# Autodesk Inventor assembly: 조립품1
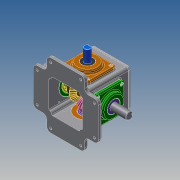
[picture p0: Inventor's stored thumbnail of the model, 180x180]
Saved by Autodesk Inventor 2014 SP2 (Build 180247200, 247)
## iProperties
Created: 2019-12
Part Number: 조립품1
Document SubType Name: Assembly
Designer: kb542-10
Mass: 4194.65 g
Surface Area: 3365.11 cm^2
Volume: 1062.39 cm^3
Density: 3.94832 g/cm^3
Author: kb542-10
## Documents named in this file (16)
- C:\Users\kb542-10\Desktop\391204V1038\조립도면.iam
- C:\Users\kb542-10\Desktop\391204V1038\본체.ipt
- C:\Users\kb542-10\Desktop\391204V1038\개스킷.ipt
- C:\Users\kb542-10\Desktop\391204V1038\메인베벨기어.ipt
- C:\Users\kb542-10\Desktop\391204V1038\메인축.ipt
- C:\Users\kb542-10\Desktop\391204V1038\메인커버.ipt
- C:\Users\kb542-10\Desktop\391204V1038\베어링 6203.ipt
- C:\Users\kb542-10\Desktop\391204V1038\베어링 6204.ipt
- C:\Users\kb542-10\Desktop\391204V1038\볼트 M4.ipt
- C:\Users\kb542-10\Desktop\391204V1038\상부커버.ipt
- C:\Users\kb542-10\Desktop\391204V1038\서브베벨기어.ipt
- C:\Users\kb542-10\Desktop\391204V1038\서브축.ipt
- C:\Users\kb542-10\Desktop\391204V1038\서브커버.ipt
- C:\Users\kb542-10\Desktop\391204V1038\오일 실 17 32 8.ipt
- C:\Users\kb542-10\Desktop\391204V1038\오일 실 20 35 8.ipt
- C:\Users\kb542-10\Desktop\391204V1038\키 4x4.ipt
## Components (1 placed, 1 different names)
1. 개스킷:1
